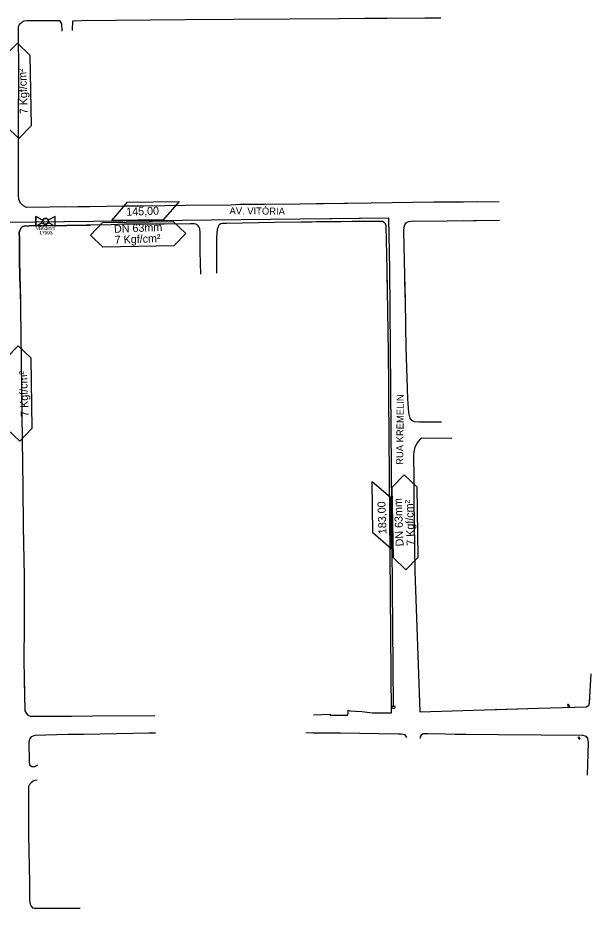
# Model space of a CAD drawing. Extents: x 325899 to 364828, y 7568995 to 7592502.
# Drawn here: x 359011 to 359762, y 7573684 to 7574852 of the extents above; entities that cross this region are included whole.
import ezdxf

# ---------------------------------------------------------------- set-up
doc = ezdxf.new("R2010")
doc.units = 0
for name, color, linetype in [('MEIO_FIO_GUIA', 7, 'Continuous'), ('PLACA_SINALIZACAO', 7, 'Continuous'), ('SIMBOLO', 7, 'Continuous'), ('TEXTO', 7, 'Continuous'), ('TUBO_PEAD_GN_63', 7, 'Continuous'), ('VALVULA_PEAD_63', 7, 'Continuous')]:
    doc.layers.add(name, color=color, linetype=linetype)

# ---------------------------------------------------------------- blocks, each defined once
blk = doc.blocks.new('PLACA')
at = {"layer": 'PLACA_SINALIZACAO'}
for p, q in [((0.15, -0.47), (0.15, 0.47)), ((0.15, -0.47), (0.15, 0.47)), ((0.22, 0.47), (0.22, -0.47)), ((0.22, 0.47), (0.22, -0.47))]:
    blk.add_line(p, q, dxfattribs=at)
blk.add_circle((0, 0), 0.153, dxfattribs=at)
blk.add_circle((0, 0), 0.153, dxfattribs=at)
for centre, start, end in [((0.19, 0.47), 359.9997, 179.9997), ((0.19, 0.47), 359.9997, 179.9997), ((0.19, -0.47), 179.9997, 359.9997), ((0.19, -0.47), 179.9997, 359.9997)]:
    blk.add_arc(centre, 0.0359, start, end, dxfattribs=at)
blk = doc.blocks.new('VALVULA_PEAD_DN_63_1')
for points in [[(-1.14, 0.57), (-4.25, 2.13), (-4.25, -2.13), (-1.14, -0.57)], [(-1.14, -0.57), (-4.25, -2.13), (-4.25, 2.13), (-1.14, 0.57)], [(1.14, -0.57), (4.25, -2.13), (4.25, 2.13), (1.14, 0.57)], [(1.14, -0.57), (4.25, -2.13), (4.25, 2.13), (1.14, 0.57)]]:
    blk.add_lwpolyline(points)
blk.add_circle((0, 0), 1.28)
for start, end in [(90, 270), (153.4349, 180), (180, 206.5651), (270, 90), (0, 26.5651), (333.4349, 360)]:
    blk.add_arc((0, 0), 1.28, start, end)

msp = doc.modelspace()

# ---------------------------------------------------------------- linework, layer by layer
at = {"layer": 'MEIO_FIO_GUIA'}
for p, q in [((359409.9, 7574584), (359401.8, 7574583.9)), ((359434, 7574583.9), (359409.9, 7574584)), ((359448.8, 7574584.3), (359434, 7574583.9)), ((359475.8, 7574584.5), (359448.8, 7574584.3)), ((359486, 7574584.6), (359475.8, 7574584.5)), ((359488.3, 7574584.4), (359486, 7574584.6)), ((359490.6, 7574583.4), (359488.3, 7574584.4)), ((359492.6, 7574581.4), (359490.6, 7574583.4)), ((359493.4, 7574579), (359492.6, 7574581.4)), ((359494.4, 7574521.3), (359493.4, 7574579)), ((359516.3, 7574572.3), (359516.9, 7574577)), ((359516.9, 7574577), (359517.9, 7574580.2)), ((359517.9, 7574580.2), (359519.7, 7574582.6)), ((359519.7, 7574582.6), (359522.7, 7574584.6)), ((359522.7, 7574584.6), (359526, 7574584.9)), ((359526, 7574584.9), (359573, 7574585.4)), ((359573, 7574585.4), (359594.8, 7574585.7)), ((359517.8, 7574513.3), (359516.3, 7574572.3)), ((359496.3, 7574413.1), (359494.4, 7574521.3)), ((359518.4, 7574481.4), (359517.8, 7574513.3)), ((359013.7, 7574497.1), (359014, 7574482.9)), ((359518.9, 7574447.3), (359518.4, 7574481.4)), ((359519.6, 7574419.8), (359518.9, 7574447.3)), ((359496.8, 7574369.8), (359496.3, 7574413.1)), ((359521.8, 7574352), (359519.6, 7574419.8)), ((359496.9, 7574354), (359496.8, 7574369.8)), ((359500.3, 7573940.2), (359496.9, 7574354)), ((359523.2, 7574333.6), (359521.8, 7574352)), ((359524.7, 7574326.4), (359523.2, 7574333.6)), ((359526.8, 7574323.4), (359524.7, 7574326.4)), ((359530.5, 7574321.9), (359526.8, 7574323.4)), ((359536.9, 7574321.4), (359530.5, 7574321.9)), ((359565.8, 7574321.5), (359536.9, 7574321.4)), ((359537, 7574298.1), (359534.3, 7574294.9)), ((359540.1, 7574300.2), (359537, 7574298.1)), ((359579.4, 7574300.1), (359540.1, 7574300.2)), ((359531, 7574288.8), (359529.5, 7574282.6)), ((359534.3, 7574294.9), (359531, 7574288.8)), ((359529.5, 7574282.6), (359529, 7574279)), ((359529, 7574279), (359529.6, 7574246.9)), ((359529.6, 7574246.9), (359529.5, 7574217)), ((359529.5, 7574217), (359530.1, 7574189.4)), ((359530.1, 7574189.4), (359530.8, 7574126.1)), ((359398, 7573937.8), (359420, 7573938.5)), ((359420, 7573938.5), (359420.1, 7573937.1)), ((359420.1, 7573937.1), (359443, 7573937)), ((359443, 7573937), (359443.3, 7573940.1)), ((359443.3, 7573940.1), (359443.5, 7573943.9)), ((359443.5, 7573943.9), (359445.5, 7573942.9)), ((359445.5, 7573942.9), (359452.9, 7573942.3)), ((359452.9, 7573942.3), (359461.5, 7573942)), ((359461.5, 7573942), (359475.5, 7573940.4)), ((359475.5, 7573940.4), (359500.3, 7573940.2))]:
    msp.add_line(p, q, dxfattribs=at)
for points in [[(359071.8, 7574603.6), (359052.6, 7574603.4), (359022, 7574603), (359018, 7574604.9), (359014.1, 7574608.5), (359012, 7574613.9), (359011.6, 7574619.4), (359011.6, 7574649), (359011.7, 7574694.5), (359011.6, 7574719.1), (359012.1, 7574772.5), (359011.7, 7574839.6), (359013, 7574843.1), (359015.8, 7574845.8), (359018.8, 7574847.5), (359022.6, 7574848.3), (359028.5, 7574848.1), (359065.5, 7574848.1), (359067.9, 7574843.5), (359068.2, 7574834.1)], [(359012.1, 7574771.4), (359012.1, 7574772.5), (359011.7, 7574839.6), (359013, 7574843.1), (359015.8, 7574845.8), (359018.8, 7574847.5), (359022.6, 7574848.3), (359028.5, 7574848.1), (359065.5, 7574848.1), (359067.9, 7574843.5), (359068.2, 7574834.1)], [(359011.8, 7574744), (359012.1, 7574772.5), (359011.7, 7574839.6), (359013, 7574843.1), (359015.8, 7574845.8), (359018.8, 7574847.5), (359022.6, 7574848.3), (359028.5, 7574848.1), (359065.5, 7574848.1), (359067.9, 7574843.5), (359068.2, 7574834.1)], [(359012.1, 7574771.4), (359012.1, 7574772.5), (359011.7, 7574839.6), (359013, 7574843.1), (359015.8, 7574845.8), (359018.8, 7574847.5), (359022.6, 7574848.3), (359028.5, 7574848.1), (359065.5, 7574848.1), (359067.9, 7574843.5), (359068.2, 7574834.1)], [(359082.2, 7574835.1), (359082.9, 7574847.6), (359094.3, 7574848.3), (359230.1, 7574849.4), (359293.7, 7574850), (359367.2, 7574850.2), (359432.3, 7574850.6), (359465.4, 7574851), (359494.4, 7574851.3), (359544.1, 7574851.5), (359564.9, 7574851.6)], [(359082.2, 7574835.1), (359082.9, 7574847.6), (359094.3, 7574848.3), (359230.1, 7574849.4), (359293.7, 7574850), (359367.2, 7574850.2), (359432.3, 7574850.6), (359465.4, 7574851), (359494.4, 7574851.3), (359544.1, 7574851.5), (359564.9, 7574851.6)], [(359082.2, 7574835.1), (359082.9, 7574847.6), (359094.3, 7574848.3), (359101.9, 7574848.4)], [(359105.2, 7574603.9), (359104.5, 7574603.9), (359089.4, 7574603.9), (359052.6, 7574603.4), (359022, 7574603), (359018, 7574604.9), (359014.1, 7574608.5), (359012, 7574613.9), (359011.6, 7574619.4), (359011.6, 7574649), (359011.7, 7574694.5), (359011.6, 7574715)], [(359071.8, 7574603.6), (359052.6, 7574603.4), (359022, 7574603), (359018, 7574604.9), (359014.1, 7574608.5), (359012, 7574613.9), (359011.6, 7574619.4), (359011.6, 7574649), (359011.7, 7574694.5), (359011.6, 7574703.7)], [(359641.5, 7574610.3), (359641.4, 7574610.3), (359555.8, 7574609.7), (359473.8, 7574608.7), (359380.2, 7574607.2), (359334.3, 7574606.8), (359308, 7574606.8), (359301.5, 7574606.9), (359290.3, 7574606), (359231, 7574605.6), (359175.6, 7574604.5), (359149.8, 7574604.5), (359104.5, 7574603.9), (359089.4, 7574603.9), (359052.6, 7574603.4), (359022, 7574603), (359018, 7574604.9), (359014.1, 7574608.5), (359012, 7574613.9), (359011.6, 7574619.4), (359011.6, 7574649), (359011.7, 7574694.5), (359011.6, 7574703.7)], [(359611.9, 7574610.1), (359555.8, 7574609.7), (359473.8, 7574608.7), (359401.9, 7574607.6)], [(359594.7, 7574610), (359555.8, 7574609.7), (359473.8, 7574608.7), (359401.9, 7574607.6)], [(359250.3, 7574515.6), (359249.7, 7574545.1), (359249.4, 7574569.7), (359249, 7574574.7), (359248.2, 7574577.2), (359246.4, 7574579.3), (359243.7, 7574581.1), (359241.6, 7574581.6), (359236.8, 7574581.6), (359202.5, 7574580.9), (359150.3, 7574581), (359133.1, 7574580.2), (359100.8, 7574579.7), (359074.3, 7574579.3), (359025.7, 7574578.7), (359018.9, 7574578.5), (359016.7, 7574578), (359014.9, 7574576.1), (359013.4, 7574572.9), (359012.5, 7574569.9), (359012.9, 7574562.3), (359013, 7574532.9), (359013.7, 7574497.1)], [(359013.7, 7574497.1), (359013, 7574532.9), (359012.9, 7574562.3), (359012.5, 7574569.9), (359013.4, 7574572.9), (359014.9, 7574576.1), (359016.7, 7574578), (359018.9, 7574578.5), (359025.7, 7574578.7), (359074.3, 7574579.3), (359100.8, 7574579.7), (359105.6, 7574579.8)], [(359013.7, 7574497.1), (359013, 7574532.9), (359012.9, 7574562.3), (359012.5, 7574569.9), (359013.4, 7574572.9), (359014.9, 7574576.1), (359016.7, 7574578), (359018.9, 7574578.5), (359025.7, 7574578.7), (359072.1, 7574579.3)], [(359072.1, 7574579.3), (359025.7, 7574578.7), (359018.9, 7574578.5), (359016.7, 7574578), (359014.9, 7574576.1), (359013.4, 7574572.9), (359012.5, 7574569.9), (359012.9, 7574562.3), (359013, 7574532.9), (359013.7, 7574497.1)], [(359494.9, 7574494.6), (359494.4, 7574521.3), (359493.4, 7574579), (359492.6, 7574581.4), (359490.6, 7574583.4), (359488.3, 7574584.4), (359486, 7574584.6), (359475.8, 7574584.5), (359448.8, 7574584.3), (359434, 7574583.9), (359409.9, 7574584), (359395.7, 7574583.7), (359381.5, 7574583.5), (359347, 7574583), (359284.1, 7574581.9), (359278.6, 7574581.9), (359276.5, 7574581.5), (359274.5, 7574580), (359273, 7574577.3), (359272, 7574574.1), (359270.9, 7574564), (359271, 7574520.1), (359271, 7574516.9)], [(359494.9, 7574494.6), (359494.4, 7574521.3), (359493.4, 7574579), (359492.6, 7574581.4), (359490.6, 7574583.4), (359488.3, 7574584.4), (359486, 7574584.6), (359475.8, 7574584.5), (359448.8, 7574584.3), (359434, 7574583.9), (359409.9, 7574584), (359395.7, 7574583.7), (359384.8, 7574583.5)], [(359495, 7574485.5), (359494.4, 7574521.3), (359493.4, 7574579), (359492.6, 7574581.4), (359490.6, 7574583.4), (359488.3, 7574584.4), (359486, 7574584.6), (359475.8, 7574584.5), (359448.8, 7574584.3), (359434, 7574583.9), (359409.9, 7574584), (359401.8, 7574583.9)], [(359518.2, 7574494.7), (359517.8, 7574513.3), (359516.3, 7574572.3), (359516.9, 7574577), (359517.9, 7574580.2), (359519.7, 7574582.6), (359522.7, 7574584.6), (359526, 7574584.9), (359573, 7574585.4), (359641.7, 7574586.4)], [(359518.3, 7574485.6), (359517.8, 7574513.3), (359516.3, 7574572.3), (359516.9, 7574577), (359517.9, 7574580.2), (359519.7, 7574582.6), (359522.7, 7574584.6), (359526, 7574584.9), (359573, 7574585.4), (359611.8, 7574586)], [(359013.7, 7574497.1), (359014.7, 7574438.6), (359015.6, 7574364), (359016.3, 7574298.3), (359017.2, 7574236.1), (359017.8, 7574185.1), (359018.9, 7574119.1), (359019.2, 7574056.6), (359018.7, 7574008.2)], [(359530.8, 7574126.1), (359537.2, 7573941.4), (359692.5, 7573946.2), (359755.9, 7573948.2), (359758.6, 7573950.3), (359759.5, 7573953.2), (359761.9, 7573991.3)], [(359018.7, 7574008.2), (359019.8, 7573942.8), (359022, 7573939.4), (359023.7, 7573937.3), (359026.9, 7573935.7), (359076.7, 7573936)], [(359018.7, 7574008.2), (359019.8, 7573942.8), (359022, 7573939.4), (359023.7, 7573937.3), (359026.9, 7573935.7), (359052.4, 7573935.9)], [(359019.1, 7573983.4), (359019.8, 7573942.8), (359022, 7573939.4), (359023.7, 7573937.3), (359026.9, 7573935.7), (359080.9, 7573936)], [(359019.1, 7573983.4), (359019.8, 7573942.8), (359022, 7573939.4), (359023.7, 7573937.3), (359026.9, 7573935.7), (359190.3, 7573936.5)], [(359624.9, 7573944.1), (359692.5, 7573946.2), (359755.9, 7573948.2), (359758.6, 7573950.3), (359759.5, 7573953.2), (359761.9, 7573991.3)], [(359191, 7573913.7), (359182.4, 7573913.4), (359097.7, 7573911.9), (359076.5, 7573911.7), (359061.7, 7573911.4), (359033.1, 7573910.7), (359028.1, 7573908.9), (359026.5, 7573906.5), (359025.1, 7573902.1), (359025.4, 7573875.8), (359025.8, 7573871.9), (359029.2, 7573869.8), (359032.9, 7573869.7), (359036.8, 7573872.1)], [(359081.2, 7573911.8), (359076.5, 7573911.7), (359061.7, 7573911.4), (359033.1, 7573910.7), (359028.1, 7573908.9), (359026.5, 7573906.5), (359025.1, 7573902.1), (359025.4, 7573875.8), (359025.8, 7573871.9), (359029.2, 7573869.8), (359032.9, 7573869.7), (359036.8, 7573872.1)], [(359076.8, 7573911.7), (359076.5, 7573911.7), (359061.7, 7573911.4), (359033.1, 7573910.7), (359028.1, 7573908.9), (359026.5, 7573906.5), (359025.1, 7573902.1), (359025.4, 7573875.8), (359025.8, 7573871.9), (359029.2, 7573869.8), (359032.9, 7573869.7), (359036.8, 7573872.1)], [(359076.8, 7573911.7), (359076.5, 7573911.7), (359061.7, 7573911.4), (359033.1, 7573910.7), (359028.1, 7573908.9), (359026.5, 7573906.5), (359025.1, 7573902.1), (359025.4, 7573875.8), (359025.8, 7573871.9), (359029.2, 7573869.8), (359032.9, 7573869.7), (359036.8, 7573872.1)], [(359520.4, 7573907.7), (359518.1, 7573911.2), (359512.9, 7573912.4), (359508.8, 7573912.4), (359433.3, 7573913.4), (359401.5, 7573913.7), (359388.1, 7573913.8)], [(359520.4, 7573907.7), (359518.1, 7573911.2), (359512.9, 7573912.4), (359508.8, 7573912.4), (359433.3, 7573913.4), (359401.5, 7573913.7), (359397.8, 7573913.7)], [(359546.2, 7573912.7), (359541.9, 7573912.8), (359540.8, 7573912.3), (359539.2, 7573911), (359538.3, 7573909.8), (359537.9, 7573908.8), (359537.8, 7573906.7)], [(359598.1, 7573911.9), (359596.1, 7573912), (359571.1, 7573912.1), (359547.7, 7573912.7), (359541.9, 7573912.8), (359540.8, 7573912.3), (359539.2, 7573911), (359538.3, 7573909.8), (359537.9, 7573908.8), (359537.8, 7573906.7)], [(359757.2, 7573858.6), (359758.2, 7573901.5), (359757.7, 7573906.4), (359755.8, 7573909.3), (359750.8, 7573910.3), (359696.5, 7573911), (359583.6, 7573912)], [(359036.2, 7573851.8), (359033.1, 7573851.5), (359030.8, 7573850.4), (359028.2, 7573848.4), (359026, 7573846.4), (359024.8, 7573843.8), (359024.8, 7573840.1), (359024.8, 7573818.9)], [(359036.2, 7573851.8), (359033.1, 7573851.5), (359030.8, 7573850.4), (359028.2, 7573848.4), (359026, 7573846.4), (359024.8, 7573843.8), (359024.8, 7573840.1), (359024.8, 7573811.6), (359024.8, 7573780.5), (359025.8, 7573717.2), (359026, 7573694.2), (359026.9, 7573689.1), (359028.2, 7573686.7), (359030.1, 7573684.6), (359032.2, 7573684), (359038.8, 7573684.1), (359092.3, 7573684.1)], [(359036.2, 7573851.8), (359033.1, 7573851.5), (359030.8, 7573850.4), (359028.2, 7573848.4), (359026, 7573846.4), (359024.8, 7573843.8), (359024.8, 7573840.1), (359024.8, 7573825.8)], [(359036.2, 7573851.8), (359033.1, 7573851.5), (359030.8, 7573850.4), (359028.2, 7573848.4), (359026, 7573846.4), (359024.8, 7573843.8), (359024.8, 7573840.1), (359024.8, 7573825.8)]]:
    msp.add_lwpolyline(points, dxfattribs=at)
at = {"layer": 'SIMBOLO'}
for points in [[(359012.1, 7574693.5), (358995.8, 7574709.3), (358994.3, 7574802.1), (359010.2, 7574818.4), (359026.5, 7574802.6), (359028, 7574709.8), (359012.1, 7574693.5)], [(359105.8, 7574566.8), (359121.6, 7574583.2), (359214.4, 7574584.6), (359230.7, 7574568.8), (359214.9, 7574552.5), (359122.1, 7574551), (359105.8, 7574566.8)], [(359013.2, 7574296.6), (358996.9, 7574312.4), (358995.5, 7574405.2), (359011.3, 7574421.5), (359027.6, 7574405.7), (359029.1, 7574312.9), (359013.2, 7574296.6)], [(359519, 7574127.6), (359502.7, 7574143.4), (359501.2, 7574236.1), (359517, 7574252.5), (359533.3, 7574236.7), (359534.8, 7574143.9), (359519, 7574127.6)]]:
    msp.add_lwpolyline(points, dxfattribs=at)
for points in [[(359201.2, 7574586.8), (359133.7, 7574585.9), (359154.4, 7574609.9), (359221.9, 7574610.8)], [(359499, 7574222.9), (359499.9, 7574155.4), (359475.9, 7574176.2), (359475.1, 7574243.6)]]:
    msp.add_lwpolyline(points, close=True, dxfattribs=at)
at = {"layer": 'TUBO_PEAD_GN_63'}
for p, q in [((359496.8, 7574588.9), (358993.8, 7574583.1)), ((359496.8, 7574588.9), (359384.8, 7574587.6)), ((359072, 7574584), (358993.8, 7574583.1)), ((359505.3, 7573948.4), (359500.4, 7573948.4))]:
    msp.add_line(p, q, dxfattribs=at)
msp.add_lwpolyline([(359502.8, 7573948.4), (359497.9, 7574521.4), (359496.8, 7574588.9)], dxfattribs=at)
msp.add_arc((359502.8, 7573948.4), 2.44, 179.8591, 359.8591, dxfattribs=at)

# ---------------------------------------------------------------- block references
at = {"layer": 'PLACA_SINALIZACAO', "xscale": 3.500000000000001, "yscale": 3.5000000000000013, "rotation": 30.813986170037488}
for p in [(359731.8, 7573949.6), (359745.5, 7573907)]:
    msp.add_blockref('PLACA', p, dxfattribs=at)
at = {"layer": 'VALVULA_PEAD_63', "xscale": 3, "yscale": 3}
msp.add_blockref('VALVULA_PEAD_DN_63_1', (359047, 7574584.7), dxfattribs=at)

# ---------------------------------------------------------------- texts
at = {"layer": 'TEXTO'}
for s, height, rotation, p in [('7 Kgf/cm²', 10.5, 92.2907, (359023.9, 7574725.5)), ('145,00', 10.5, 2.0817, (359152.9, 7574592)), ('AV. VITÓRIA', 9.221, 359.5098, (359288, 7574594)), ('DN 63mm', 10.5, 2.2907, (359136.9, 7574569.6)), ('7 Kgf/cm²', 10.5, 2.2907, (359137.8, 7574555.1)), ('7 Kgf/cm²', 10.5, 92.2907, (359025, 7574328.6)), ('RUA KREMELIN', 9.221, 89.5098, (359515.6, 7574265.4)), ('183,00', 10.5, 92.0817, (359493.8, 7574174.7)), ('DN 63mm', 10.5, 92.2907, (359516.2, 7574158.7)), ('7 Kgf/cm²', 10.5, 92.2907, (359530.7, 7574159.6))]:
    msp.add_text(s, height=height, rotation=rotation, dxfattribs=at).set_placement(p)
at = {"layer": 'VALVULA_PEAD_63'}
for s, p in [('VB63mm', (359034.3, 7574573.5)), ('17993', (359038.8, 7574567.5))]:
    msp.add_text(s, height=4.5, dxfattribs=at).set_placement(p)

doc.saveas('drawing.dxf')
